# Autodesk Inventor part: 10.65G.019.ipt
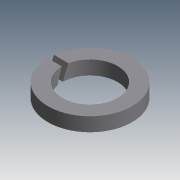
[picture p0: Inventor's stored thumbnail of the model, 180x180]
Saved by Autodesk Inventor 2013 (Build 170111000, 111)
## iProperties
Shininess: 25.0
Length Units: 11269
Angle Units: 11279
Time Units: 11290
Mass Units: 11283
Length Display Precision: 3
Angle Display Precision: 2
Created: 2001-04
Material: Steel, Mild
Document SubType Name: Modeling
Designer: tevgeniy
Mass: 1.96655 g
Surface Area: 4.06504 cm^2
Volume: 0.250197 cm^3
Density: 7.86 g/cm^3
Part Number: 10.65G.019.ipt
Density: 7.86
Volumn: 0.2501956736428592
Area: 4.065041569612211
PropertySet Name: Model Information
Control State: 0
Master: False
Checked Out: False
Last Check In Date: 2008-10-15
Checked Out Date: 2008-10-15
Author: tevgeniy
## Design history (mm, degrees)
node "ExtrusionBlind1" dims "d2" = 2.5, "d3" = 0
  sketch "Sketch1"
    geometry: C1 r 7.6 at (-266.435, -313.047)
    constraints: 1 centre point, 1 other
    dimensions: "d1" = 15.2 diameter of C1
node "Hole1" dims "d5" = 10, "d6" = 4, "d7" = 2, "d8" = 60 deg, "d9" = 8, "d10" = 118 deg
  sketch "Sketch2"
    geometry: C1 r 7.6 at (0, 0) reference
node "WorkPlane1"
node "ExtrusionToFace1" dims "d18" = 0.13, "d19" = 0
  sketch "Sketch3"
    geometry: L1 (-21.641, 0.09)-(-21.641, -1); L2 (-19.141, 1)-(-21.641, 0.09); L3 (-19.141, -0.09)-(-19.141, 1); L4 (-21.641, -1)-(-19.141, -0.09); L5 (-9.571, 0)-(-31.211, 0); C1 r 7.6 at (-19.141, 0); C2 r 7.6 at (-21.641, 0)
    constraints: 10 end point, 2 centre point, 2 parallel, 1 vertical
    dimensions: "d13" = 0 horizontal distance of L2.start C1.centre; "d15" = 0 horizontal distance of L1.start C2.centre; "d17" = 160 deg angle of L4 L5
body "Solid1"
other parameters: "d0" = 15.2 (derived), "d4" = 0, "d12" = 0 (derived), "d14" = 0 (derived), "d16" = 160 deg (derived), "d20" = 0
